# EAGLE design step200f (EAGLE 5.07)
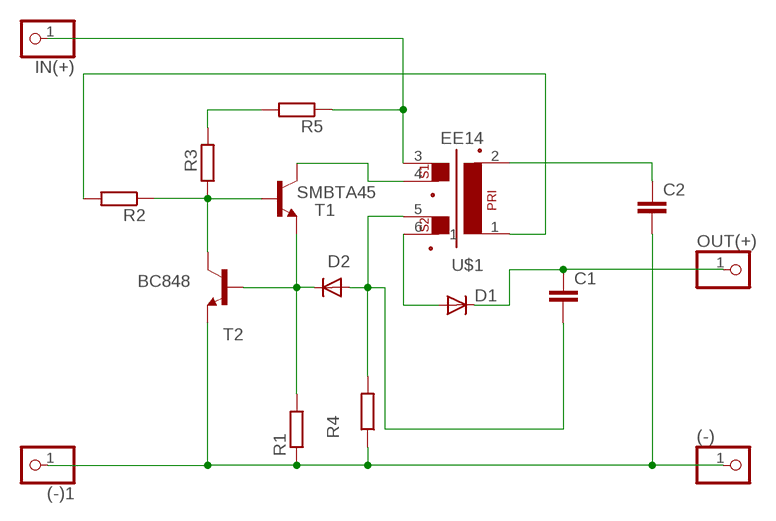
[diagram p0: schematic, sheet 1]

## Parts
(-)  PINHD-1X11MM6  [1X1MM8]
(-)1  PINHD-1X11MM6  [1X1MM8]
C1  C-EU025-025X050  [C025-025X050]
C2  C-EUC0805  [C0805]
D1  DIODE-SMA-DO214  [SMA-DO214AC]
D2  DIODE-MINIMELF  [MINIMELF]
IN(+)  PINHD-1X11MM6  [1X1MM8]
OUT(+)  PINHD-1X11MM6  [1X1MM8]
R1  R-EU_R0805  [R0805]
R2  R-EU_R0805  [R0805]
R3  R-EU_R1206  [R1206]
R4  R-EU_R0805  [R0805]
R5  R-EU_R1206  [R1206]
T1  SMBTA45  BC848  [SOT23]
T2  BC848  [SOT23]
U$1  EE14  [EE14]

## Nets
A: D1.A U$1.6
B1C2: R2.1 R3.1 T1.B T2.C
C1: T1.C U$1.4
EB: D2.C R1.2 T1.E T2.B
N$1: R3.2 R5.2
N$4: R2.2 U$1.1
N$6: C2.1 U$1.2
NDOT: C1.2 D2.A R4.2 U$1.5
V+: IN(+).1 R5.1 U$1.3
V-: (-)1.1 (-).1 C2.2 R1.1 R4.1 T2.E
VOUT+: C1.1 D1.K(C) OUT(+).1

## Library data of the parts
(-) (-)1 IN(+) OUT(+) = pinhead:PINHD-1X1: PIN HEADER
C1 C2 = rcl:C-EU: CAPACITOR, European symbol
D1 D2 = diode:DIODE-: DIODE
R1-R5 = rcl:R-EU_: RESISTOR, European symbol
T1 T2 = transistor:BC848: NPN TRANSISTOR
U$1 = trafo:EE14

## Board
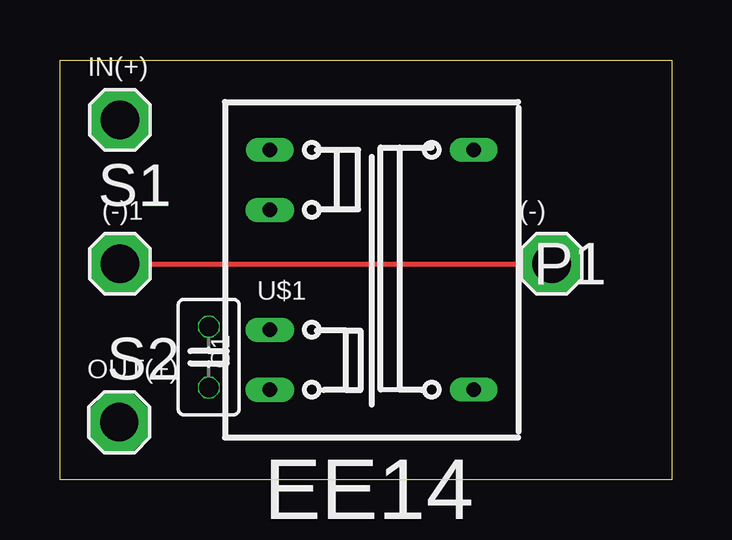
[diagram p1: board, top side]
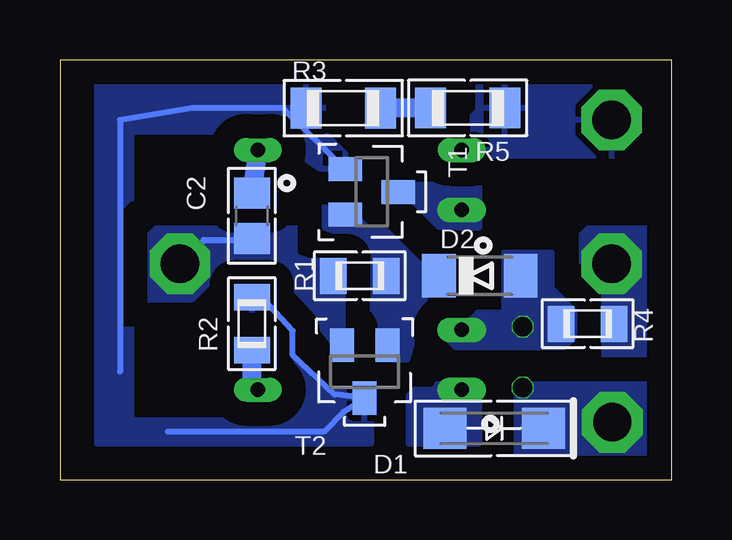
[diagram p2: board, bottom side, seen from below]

Size 25.5 x 17.5 mm. Coordinates in mm from the lower left corner, seen from the top.
Outline: 0,17.5 25.5,17.5 25.5,0 0,0 0,17.5
Copper layers (1*16): Top 0.035mm / dielectric 1.5mm / Bottom 0.035mm
Design rules "default": minimum track width 10mil, minimum drill 20mil, track to track 8mil, track to pad 8mil, pad to pad 8mil, via to via 8mil, smd to smd 8mil, copper to edge 40mil, drill to drill 8mil, minimum pad ring 1mil, minimum via ring 8mil, stop-mask expansion 4mil, vias tented up to drill 0mil, thermal gap 10mil

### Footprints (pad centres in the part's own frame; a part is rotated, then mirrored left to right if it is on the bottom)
1X1MM8 = drill 1.6 pad 2.54 octagon: 1 0,0
C025-025X050 = drill 0.813 octagon: 1 -1.27,0; 2 1.27,0
C0805 = smd 1.3 x 1.5: 1 -0.95,0; 2 0.95,0
SMA-DO214AC = smd 1.8 x 1.7: A 2.05,-0.127; K -2.05,-0.127
MINIMELF = smd 1.4 x 1.8: A 1.7,0; C -1.7,0
R0805 = smd 1.1 x 1.5: 1 -1.1,0; 2 1.1,0
R1206 = smd 1.3 x 1.7: 1 -1.55,0; 2 1.55,0
SOT23 = smd 1 x 1.4: B -0.95,-1.1; C 0,1.1; E 0.95,-1.1
EE14 = drill 0.6 pad 1 long: 1 4.25,-5; 2 4.25,5; 3 -4.25,5 | drill 0.6 pad 1.016 long: 4 -4.25,2.5; 5 -4.25,-2.5; 6 -4.25,-5

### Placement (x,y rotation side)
(-)  20.5,9 0 top
(-)1  2.5,9 0 top
C1  6.2,5.11 90 top
C2  17.5,11 270 bottom
D1  7.39,2.01 180 bottom
D2  8,8.5 0 bottom
IN(+)  2.5,15 0 top
OUT(+)  2.47,2.39 0 top
R1  13,8.5 0 bottom
R2  17.5,6.5 270 bottom
R3  13.69,15.49 0 bottom
R4  3.5,6.5 180 bottom
R5  8.5,15.5 180 bottom
T1  12.5,12 270 bottom
T2  12.8,4.5 180 bottom
U$1  13,8.75 0 top

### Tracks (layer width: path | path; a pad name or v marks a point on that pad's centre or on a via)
A
  pour Bottom (isolate 1, rank 3, no thermals): 8,4 10.5,4 11,3.5 11,1.5 8,1.5
B1C2
  Bottom 0.254: 21,2 14.5,2 13.67,2.83 T2.C 14.04,3.54 15.8,5.2 15.8,6.2 17,7.5 17.51,7.5 R2.1 | 23,4.5 23,15 20,15.5 16.19,15.5 T1.B
  pour Bottom (isolate 1, rank 3): 14.5,16.5 24,16.5 24,1.5 12.5,1.5 12.5,4.5 14,4.5 15,5.5 15.5,7 18.5,7.5 18.5,2.5 22.5,2.5 22.5,14.5 17,14.5 14,12.5 13,13 14.5,14.5
C1
  pour Bottom (isolate 1, rank 3, no thermals): 8,12.3 11,12.3 11,10.5 8,10.5
EB
  pour Bottom (isolate 1, no thermals): 11,5 10,8.5 13,11.5 14.5,11.5 14.5,10.5 13,10 12.5,9.5 12.5,5.5 12,5
N$1
  Bottom 0.8: R5.2 R3.2
N$4
  Bottom 0.8: R2.2 17.5,4 U$1.1
N$6
  Bottom 0.8: C2.1 U$1.2
NDOT
  pour Bottom (isolate 1, rank 3, no thermals): 4,7 4,6 4.5,5.5 9,5.5 9.5,6 9.5,6.5 9,7 7,7 7,9.5 5,9.5 5,8
V+
  pour Bottom (isolate 1, rank 4): 3,16.5 6,16.5 8.1,16.4 8.1,15.4 9,14.5 9.5,13.5 2,13.5
V-
  Top 0.2: (-)1.1 19.6,9 20.6,8 (-).1
  Bottom 0.254: 20.6,8.9 (-).1 19.5,10 17.93,10 C2.2
  pour Bottom (isolate 1, rank 2, no thermals): 15.5,10.5 21.5,10.5 22,10 22,7.5 20,7.5 19,8.5 16,8.5 16,7.5 15.5,7.5 15.1,6.9 14,5.5 13.2,5.4 13.3,8.3
  pour Bottom (isolate 1, rank 4, no thermals): 1,10.5 3.5,10.5 4,10 4,8.5 3,7.5 3,5 1,5 1,9.5
VOUT+
  pour Bottom (isolate 1, rank 3, no thermals): 1.5,4 6,4 6.5,3.5 6.5,0.5 1,0.5 1,4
